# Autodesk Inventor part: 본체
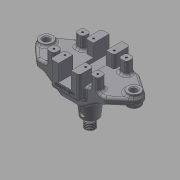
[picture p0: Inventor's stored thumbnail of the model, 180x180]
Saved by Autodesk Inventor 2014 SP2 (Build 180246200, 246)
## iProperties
Created: 2025-07
Part Number: 본체
Material: Generic
Document SubType Name: Modeling
Designer: Administrator
Density: 1 g/cm^3
Appearance: Default
Author: Administrator
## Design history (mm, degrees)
sketch "스케치8"
  geometry: L1 (-43.156, 23.794)-(43.156, 23.794); L2 (-43.156, 23.794)-(-61.618, 7.497); L3 (-60.673, -8.235)-(-40.394, -22.206); L4 (-40.394, -22.206)-(40.394, -22.206); L5 (43.156, 23.794)-(61.618, 7.497); L6 (40.394, -22.206)-(60.673, -8.235); L7 (-18, -12.206)-(18, -12.206); L8 (18, -12.206)-(18, -32.155); L9 (18, -32.155)-(-18, -32.155); L10 (-18, -32.155)-(-18, -12.206); L11 (-18, 31.845)-(18, 31.845); L12 (18, 31.845)-(18, 13.794); L13 (18, 13.794)-(-18, 13.794); L14 (-18, 13.794)-(-18, 31.845); L15 (23.496, -12.206)-(33.496, -12.206); L16 (33.496, -12.206)-(33.496, -22.206); L17 (33.496, -22.206)-(23.496, -22.206); L18 (23.496, -22.206)-(23.496, -12.206); L19 (-31.504, -22.206)-(-31.504, -12.206); L20 (-31.504, -12.206)-(-21.504, -12.206); L21 (-21.504, -12.206)-(-21.504, -22.206); L22 (-21.504, -22.206)-(-31.504, -22.206); L23 (23.496, 13.794)-(23.496, 23.794); L24 (23.496, 23.794)-(33.496, 23.794); L25 (33.496, 23.794)-(33.496, 13.794); L26 (33.496, 13.794)-(23.496, 13.794); L27 (-31.504, 13.794)-(-31.504, 23.794); L28 (-31.504, 23.794)-(-21.504, 23.794); L29 (-21.504, 23.794)-(-21.504, 13.794); L30 (-21.504, 13.794)-(-31.504, 13.794); A1 r 10 centre (55, 0) between (60.673, -8.235) and (61.618, 7.497); A2 r 10 centre (-55, 0) between (-61.618, 7.497) and (-60.673, -8.235); 11 further points
  constraints: 60 end point, 7 midpoint, 7 parallel, 5 horizontal, 4 horizontal alignment, 4 point on circle, 4 tangent, 4 vertical alignment, 3 perpendicular, 2 centre point, 2 equal length, 1 point on line, 1 vertical, 27 other
  dimensions: "d47" = 20 diameter of A2; "d48" = 20 diameter of A1; "d49" = 110 distance of A1.centre A2.centre; "d50" = 46 distance between parallel lines of L4 L1; "d52" = 76 deg angle of L3 L2; "d53" = 64 distance between parallel lines of L9 L11; "d54" = 36 distance of L7.start L7.end; "d55" = 36 distance of L12.end L13.end; "d56" = 10 distance of L15.start L15.end; "d57" = 10 distance of L15.end L16.end; "d60" = 55 distance of L17.end L19.start; "d63" = 36 distance of L17.end L23.start; "d105" = 86.31171 distance of L1.start L1.end
extrude "돌출2" new body sketch "스케치8" distance "d66" = 16; taper "d67" = 0 deg
extrude "돌출3" join sketch "스케치8" distance "d68" = 16; taper "d69" = 0 deg
extrude "돌출4" join sketch "스케치8" distance "d70" = 25; taper "d71" = 0 deg
extrude "돌출5" join sketch "스케치8" distance "d72" = 15; taper "d73" = 0 deg
extrude "돌출6" join sketch "스케치8" distance "d74" = 25; taper "d75" = 0 deg
sketch "스케치9"
  geometry: L1 (19.66, -41)-(-66.652, -41) reference; L2 (-66.652, -41)-(-66.652, -16) reference; L3 (-66.652, -16)-(-55, -16) reference; L4 (-55, -16)-(-55, 0) reference; L5 (-55, 0)-(-45, 0) reference; L6 (-45, 0)-(-45, -16) reference; L7 (-45, -16)-(-41.496, -16) reference; L8 (-41.496, -31)-(-41.496, -16) reference; L9 (-5.496, -31)-(-41.496, -31) reference; L10 (-5.496, -16)-(-5.496, -31) reference; L11 (-5.496, 0)-(-5.496, -16) reference; L12 (-41.496, 0)-(-5.496, 0) reference; L13 (-41.496, -16)-(-41.496, 0) reference; L14 (19.66, -16)-(19.66, -41) reference; L15 (10, -16)-(19.66, -16) reference; L16 (10, 0)-(10, -16) reference; L17 (0, 0)-(10, 0) reference; L18 (0, -16)-(0, 0) reference; L19 (-5.496, -16)-(0, -16) reference; L20 (-39.496, -41)-(-7.496, -41); L21 (-7.496, -41)-(15.354, -25); L22 (-39.496, -41)-(-62.347, -25); L23 (-66.652, -16)-(-55, -16) reference; L24 (-55, -16)-(-55, 0) reference; L25 (-55, 0)-(-45, 0) reference; L26 (-45, 0)-(-45, -16) reference; L27 (-45, -16)-(-41.496, -16) reference; L28 (-41.496, -31)-(-41.496, -16) reference; L29 (-5.496, -31)-(-41.496, -31) reference; L30 (-5.496, -16)-(-5.496, -31) reference; L31 (-5.496, 0)-(-5.496, -16) reference; L32 (-41.496, 0)-(-5.496, 0) reference; L33 (-41.496, -16)-(-41.496, 0) reference; L34 (10, -16)-(19.66, -16) reference; L35 (10, 0)-(10, -16) reference; L36 (0, 0)-(10, 0) reference; L37 (0, -16)-(0, 0) reference; L38 (-5.496, -16)-(0, -16) reference; L39 (15.354, -25)-(37.491, -25); L40 (-7.496, -41)-(37.491, -41); L41 (-62.347, -25)-(-88.573, -25); L42 (-88.573, -25)-(-88.573, -41); L43 (-88.573, -41)-(-39.496, -41); L44 (19.66, -16)-(19.66, -41) reference; L45 (19.66, -41)-(-66.652, -41) reference; L46 (-66.652, -41)-(-66.652, -16) reference; L47 (37.491, -25)-(47.678, -25); L48 (47.678, -25)-(47.678, -41); L49 (47.678, -41)-(37.491, -41); 2 further points
  constraints: 22 end point, 4 parallel, 3 perpendicular, 2 point on line, 1 midpoint, 1 vertical alignment
  dimensions: "d76" = 32 distance of L20.start L20.end; "d79" = 35 deg angle of L20 L21; "d80" = 9 vertical distance of L14.start L21.end; "d81" = 35 deg angle of L20 L22; "d82" = 9 vertical distance of L2.end L22.end
extrude "돌출7" cut sketch "스케치9" stored distance "d83" = 25; taper "d84" = 0 deg
sketch "스케치10"
  geometry: L1 (-33.496, 23.794)-(-23.496, 23.794) reference; L2 (-23.496, 23.794)-(-23.496, 13.794) reference; L3 (-23.496, 13.794)-(-33.496, 13.794) reference; L4 (-33.496, 13.794)-(-33.496, 23.794) reference; L5 (21.504, 23.794)-(31.504, 23.794) reference; L6 (31.504, 23.794)-(31.504, 13.794) reference; L7 (31.504, 13.794)-(21.504, 13.794) reference; L8 (21.504, 13.794)-(21.504, 23.794) reference; L9 (18, -12.206)-(18, -32.155) reference; L10 (18, -32.155)-(-18, -32.155) reference; L11 (-18, -32.155)-(-18, -12.206) reference; L12 (-18, -12.206)-(18, -12.206) reference; L13 (18, 31.845)-(18, 13.794) reference; L14 (18, 13.794)-(-18, 13.794) reference; L15 (-18, 13.794)-(-18, 31.845) reference; L16 (-18, 31.845)-(18, 31.845) reference; L17 (-23.496, -12.206)-(-23.496, -22.206) reference; L18 (-23.496, -22.206)-(-33.496, -22.206) reference; L19 (-33.496, -22.206)-(-33.496, -12.206) reference; L20 (-33.496, -12.206)-(-23.496, -12.206) reference; L21 (31.504, -22.206)-(21.504, -22.206) reference; L22 (21.504, -22.206)-(21.504, -12.206) reference; L23 (21.504, -12.206)-(31.504, -12.206) reference; L24 (31.504, -12.206)-(31.504, -22.206) reference; L25 (-8, 31.845)-(8, 31.845); L26 (8, 31.845)-(8, -32.155); L27 (8, -32.155)-(-8, -32.155); L28 (-8, -32.155)-(-8, 31.845); 2 further points
  constraints: 8 end point, 2 parallel, 2 point on line, 1 horizontal, 1 midpoint, 1 perpendicular, 1 vertical alignment
  dimensions: "d85" = 16 distance of L25.start L25.end
extrude "돌출8" cut sketch "스케치10" distance "d86" = 21; taper "d87" = 0 deg
sketch "스케치11"
  geometry: L1 (18, -32.155)-(8, -32.155) reference; L2 (8, -32.155)-(8, -12.206) reference; L3 (21.504, -22.206)-(21.504, -12.206) reference; L4 (60.673, -8.235)-(40.394, -22.206) reference; L5 (43.156, 23.794)-(61.618, 7.497) reference; L6 (18, 23.794)-(18, 13.794) reference; L7 (8, 13.794)-(8, 31.845) reference; L8 (8, 31.845)-(18, 31.845) reference; L9 (18, 31.845)-(18, 23.794) reference; L10 (8, -12.206)-(8, 13.794) reference; L11 (31.504, -22.206)-(21.504, -22.206) reference; L12 (-61.618, 7.497)-(-43.156, 23.794) reference; L13 (-40.394, -22.206)-(-60.673, -8.235) reference; L14 (-18, -22.206)-(-18, -12.206) reference; L15 (-18, -12.206)-(-8, -12.206) reference; L16 (-8, -12.206)-(-8, -32.155) reference; L17 (-8, -32.155)-(-18, -32.155) reference; L18 (-18, -32.155)-(-18, -22.206) reference; L19 (-18, 13.794)-(-18, 23.794) reference; L20 (-8, 31.845)-(-8, 13.794) reference; L21 (-18, 31.845)-(-8, 31.845) reference; L22 (-18, 23.794)-(-18, 31.845) reference; L23 (-8, 13.794)-(-8, -12.206) reference; L24 (40.394, -22.206)-(31.504, -22.206) reference; L25 (-43.156, 23.794)-(-33.496, 23.794) reference; L26 (21.504, -12.206)-(31.504, -12.206) reference; L27 (31.504, -12.206)-(31.504, -22.206) reference; L28 (18, 13.794)-(8, 13.794) reference; L29 (21.504, 23.794)-(31.504, 23.794) reference; L30 (21.504, 13.794)-(21.504, 23.794) reference; L31 (31.504, 13.794)-(21.504, 13.794) reference; L32 (31.504, 23.794)-(31.504, 13.794) reference; L33 (-8, 13.794)-(-18, 13.794) reference; L34 (21.504, -22.206)-(18, -22.206) reference; L35 (18, -12.206)-(18, -22.206) reference; L36 (18, -22.206)-(18, -32.155) reference; L37 (8, -12.206)-(18, -12.206) reference; L38 (31.504, 23.794)-(43.156, 23.794) reference; L39 (18, 23.794)-(21.504, 23.794) reference; L40 (-23.496, -12.206)-(-23.496, -22.206) reference; L41 (-18, -22.206)-(-23.496, -22.206) reference; L42 (-33.496, -12.206)-(-23.496, -12.206) reference; L43 (-33.496, -22.206)-(-33.496, -12.206) reference; L44 (-23.496, -22.206)-(-33.496, -22.206) reference; L45 (-33.496, -22.206)-(-40.394, -22.206) reference; L46 (-33.496, 23.794)-(-23.496, 23.794) reference; L47 (-23.496, 23.794)-(-18, 23.794) reference; L48 (-33.496, 13.794)-(-33.496, 23.794) reference; L49 (-23.496, 13.794)-(-33.496, 13.794) reference; L50 (-23.496, 23.794)-(-23.496, 13.794) reference; C1 r 8 at (-55, 0); C2 r 8 at (55, 0); A1 r 10 centre (55, 0) between (60.673, -8.235) and (61.618, 7.497) reference; A2 r 10 centre (-55, 0) between (-61.618, 7.497) and (-60.673, -8.235) reference; 1 further point
  constraints: 2 centre point, 1 coincident
  dimensions: "d97" = 16 diameter of C1; "d98" = 16 diameter of C2; "d99" = 110 distance of C1.centre C2.centre
  node "절단 모서리 투영7"
extrude "돌출9" join sketch "스케치11" distance "d100" = 3; taper "d101" = 0 deg
extrude "돌출10" join sketch "스케치11" distance "d102" = 12; taper "d103" = 0 deg
sketch "스케치12"
  geometry: L1 (-5.496, -31)-(-41.496, -31) reference; L2 (-41.496, -31)-(-41.496, -16) reference; L3 (-45, -16)-(-41.496, -16) reference; L4 (-45, 0)-(-45, -16) reference; L5 (-55, 0)-(-45, 0) reference; L6 (-55, -16)-(-55, 0) reference; L7 (-66.652, -16)-(-55, -16) reference; L8 (-66.652, -25)-(-66.652, -16) reference; L9 (-62.347, -25)-(-66.652, -25) reference; L10 (-39.496, -41)-(-62.347, -25) reference; L11 (-7.496, -41)-(-39.496, -41) reference; L12 (15.354, -25)-(-7.496, -41) reference; L13 (19.66, -25)-(15.354, -25) reference; L14 (19.66, -16)-(19.66, -25) reference; L15 (10, -16)-(19.66, -16) reference; L16 (10, 0)-(10, -16) reference; L17 (0, 0)-(10, 0) reference; L18 (0, -16)-(0, 0) reference; L19 (-5.496, -16)-(0, -16) reference; L20 (-5.496, 0)-(-5.496, -16) reference; L21 (-15.496, 0)-(-5.496, 0) reference; L22 (-15.496, -21)-(-15.496, 0) reference; L23 (-31.496, -21)-(-15.496, -21) reference; L24 (-31.496, 0)-(-31.496, -21) reference; L25 (-41.496, 0)-(-31.496, 0) reference; L26 (-41.496, -16)-(-41.496, 0) reference; L27 (-5.496, -16)-(-5.496, -31) reference; 1 further point
  node "절단 모서리 투영8"
fillet "모깎기10" dims "d106" = 3
fillet "모깎기11" dims "d107" = 3
fillet "모깎기12" dims "d108" = 3
fillet "모깎기13" dims "d109" = 3
fillet "모깎기14" dims "d110" = 3
fillet "모깎기15" dims "d111" = 3
fillet "모깎기16" dims "d112" = 3
fillet "모깎기17" dims "d113" = 3
fillet "모깎기18" dims "d114" = 3
fillet "모깎기19" dims "d115" = 3
fillet "모깎기20" dims "d116" = 3
fillet "모깎기21" dims "d117" = 3
sketch "스케치13"
  geometry: L1 (-26.496, -22.206)-(-30.496, -22.206) reference; L2 (-33.496, -19.206)-(-33.496, -15.206) reference; L3 (-30.496, -12.206)-(-26.496, -12.206) reference; L4 (-23.496, -15.206)-(-23.496, -19.206) reference; L5 (-15, 31.845)-(-8, 31.845) reference; L6 (-8, 31.845)-(-8, 13.794) reference; L7 (-8, 13.794)-(-18, 13.794) reference; L8 (-18, 13.794)-(-18, 28.845) reference; L9 (18, 28.845)-(18, 16.794) reference; L10 (15, 13.794)-(8, 13.794) reference; L11 (8, 13.794)-(8, 31.845) reference; L12 (8, 31.845)-(15, 31.845) reference; L13 (24.504, -12.206)-(28.504, -12.206) reference; L14 (31.504, -15.206)-(31.504, -19.206) reference; L15 (28.504, -22.206)-(24.504, -22.206) reference; L16 (21.504, -19.206)-(21.504, -15.206) reference; L17 (21.504, 16.794)-(21.504, 20.794) reference; L18 (24.504, 23.794)-(28.504, 23.794) reference; L19 (31.504, 20.794)-(31.504, 16.794) reference; L20 (28.504, 13.794)-(24.504, 13.794) reference; L21 (-33.496, 16.794)-(-33.496, 20.794) reference; L22 (-30.496, 23.794)-(-26.496, 23.794) reference; L23 (-23.496, 20.794)-(-23.496, 16.794) reference; L24 (-26.496, 13.794)-(-30.496, 13.794) reference; L25 (-8, -12.206)-(-8, -32.155) reference; L26 (-8, -32.155)-(-18, -32.155) reference; L27 (-18, -32.155)-(-18, -12.206) reference; L28 (-18, -12.206)-(-8, -12.206) reference; L29 (8, -32.155)-(8, -12.206) reference; L30 (8, -12.206)-(15, -12.206) reference; L31 (18, -15.206)-(18, -29.155) reference; L32 (15, -32.155)-(8, -32.155) reference; C1 r 4 at (-55, 0); C2 r 4 at (55, 0); A1 r 8 centre (55, 0) between (53.743, 7.901) and (52.806, -7.693) reference; A2 r 8 centre (55, 0) between (52.806, -7.693) and (53.743, 7.901) reference; A3 r 8 centre (-55, 0) between (-52.806, -7.693) and (-53.743, 7.901) reference; A4 r 8 centre (-55, 0) between (-53.743, 7.901) and (-52.806, -7.693) reference; A5 r 3 centre (-26.496, -19.206) between (-26.496, -22.206) and (-23.496, -19.206) reference; A6 r 3 centre (-30.496, -19.206) between (-33.25, -20.397) and (-30.628, -22.203) reference; A7 r 3 centre (-30.496, -19.206) between (-30.628, -22.203) and (-30.496, -22.206) reference; A8 r 3 centre (-30.496, -19.206) between (-33.496, -19.206) and (-33.25, -20.397) reference; A9 r 3 centre (-30.496, -15.206) between (-30.496, -12.206) and (-33.496, -15.206) reference; A10 r 3 centre (-26.496, -15.206) between (-23.496, -15.206) and (-26.496, -12.206) reference; A11 r 3 centre (-15, 28.845) between (-15, 31.845) and (-18, 28.845) reference; A12 r 3 centre (15, 16.794) between (15, 13.794) and (18, 16.794) reference; A13 r 3 centre (15, 28.845) between (18, 28.845) and (15, 31.845) reference; A14 r 3 centre (24.504, -15.206) between (24.504, -12.206) and (21.504, -15.206) reference; A15 r 3 centre (28.504, -15.206) between (31.504, -15.206) and (28.504, -12.206) reference; A16 r 3 centre (28.504, -19.206) between (28.504, -22.206) and (31.504, -19.206) reference; A17 r 3 centre (24.504, -19.206) between (21.504, -19.206) and (24.504, -22.206) reference; A18 r 3 centre (24.504, 16.794) between (21.504, 16.794) and (24.504, 13.794) reference; A19 r 3 centre (24.504, 20.794) between (24.504, 23.794) and (21.504, 20.794) reference; A20 r 3 centre (28.504, 20.794) between (31.504, 20.794) and (28.504, 23.794) reference; A21 r 3 centre (28.504, 16.794) between (28.504, 13.794) and (31.504, 16.794) reference; A22 r 3 centre (-30.496, 16.794) between (-33.496, 16.794) and (-30.496, 13.794) reference; A23 r 3 centre (-30.496, 20.794) between (-30.496, 23.794) and (-33.496, 20.794) reference; A24 r 3 centre (-26.496, 20.794) between (-23.496, 20.794) and (-26.496, 23.794) reference; A25 r 3 centre (-26.496, 16.794) between (-26.496, 13.794) and (-23.496, 16.794) reference; A26 r 3 centre (15, -15.206) between (18, -15.206) and (15, -12.206) reference; A27 r 3 centre (15, -29.155) between (15, -32.155) and (18, -29.155) reference; 1 further point
  constraints: 2 centre point, 2 coincident
  dimensions: "d118" = 8 diameter of C1; "d119" = 8 diameter of C2
hole "구멍1" sketch "스케치13" at (55, 0), (-55, 0) diameter "d120" = 8; stored, may be unused: countersink angle "d124" = 82 deg, drill point angle "d126" = 0 deg; dims "d121" = 6, "d122" = 3.023, "d123" = 2, "d125" = 8
chamfer "모따기1" distance "d127" = 1; stored, may be unused: second distance "d128" = 2, angle "d129" = 45 deg
chamfer "모따기2" distance "d130" = 1; stored, may be unused: second distance "d131" = 2, angle "d132" = 45 deg
chamfer "모따기3" distance "d133" = 1; stored, may be unused: second distance "d134" = 2, angle "d135" = 45 deg
chamfer "모따기4" distance "d136" = 1; stored, may be unused: second distance "d137" = 2, angle "d138" = 45 deg
sketch "스케치14"
  geometry: L1 (-15, 31.845)-(-8, 31.845) reference; L2 (-8, 31.845)-(-8, 13.794) reference; L3 (-8, 13.794)-(-18, 13.794) reference; L4 (-18, 13.794)-(-18, 28.845) reference; L5 (18, 28.845)-(18, 16.794) reference; L6 (15, 13.794)-(8, 13.794) reference; L7 (8, 13.794)-(8, 31.845) reference; L8 (8, 31.845)-(15, 31.845) reference; L9 (31.504, -15.206)-(31.504, -19.206) reference; L10 (28.504, -22.206)-(24.504, -22.206) reference; L11 (21.504, -19.206)-(21.504, -15.206) reference; L12 (24.504, -12.206)-(28.504, -12.206) reference; L13 (28.504, 13.794)-(24.504, 13.794) reference; L14 (21.504, 16.794)-(21.504, 20.794) reference; L15 (24.504, 23.794)-(28.504, 23.794) reference; L16 (31.504, 20.794)-(31.504, 16.794) reference; L17 (-23.496, -15.206)-(-23.496, -19.206) reference; L18 (-26.496, -22.206)-(-30.496, -22.206) reference; L19 (-33.496, -19.206)-(-33.496, -15.206) reference; L20 (-30.496, -12.206)-(-26.496, -12.206) reference; L21 (-26.496, 13.794)-(-30.496, 13.794) reference; L22 (-33.496, 16.794)-(-33.496, 20.794) reference; L23 (-30.496, 23.794)-(-26.496, 23.794) reference; L24 (-23.496, 20.794)-(-23.496, 16.794) reference; L25 (-8, -12.206)-(-8, -32.155) reference; L26 (-8, -32.155)-(-18, -32.155) reference; L27 (-18, -32.155)-(-18, -12.206) reference; L28 (-18, -12.206)-(-8, -12.206) reference; L29 (8, -32.155)-(8, -12.206) reference; L30 (8, -12.206)-(15, -12.206) reference; L31 (18, -15.206)-(18, -29.155) reference; L32 (15, -32.155)-(8, -32.155) reference; A1 r 3 centre (-15, 28.845) between (-15, 31.845) and (-18, 28.845) reference; A2 r 3 centre (15, 16.794) between (15, 13.794) and (18, 16.794) reference; A3 r 3 centre (15, 28.845) between (18, 28.845) and (15, 31.845) reference; A4 r 3 centre (28.504, -15.206) between (31.504, -15.206) and (28.504, -12.206) reference; A5 r 3 centre (28.504, -19.206) between (28.504, -22.206) and (31.504, -19.206) reference; A6 r 3 centre (24.504, -19.206) between (21.504, -19.206) and (24.504, -22.206) reference; A7 r 3 centre (24.504, -15.206) between (24.504, -12.206) and (21.504, -15.206) reference; A8 r 3 centre (28.504, 16.794) between (28.504, 13.794) and (31.504, 16.794) reference; A9 r 3 centre (24.504, 16.794) between (21.504, 16.794) and (24.504, 13.794) reference; A10 r 3 centre (24.504, 20.794) between (24.504, 23.794) and (21.504, 20.794) reference; A11 r 3 centre (28.504, 20.794) between (31.504, 20.794) and (28.504, 23.794) reference; A12 r 3 centre (-26.496, -15.206) between (-23.496, -15.206) and (-26.496, -12.206) reference; A13 r 3 centre (-26.496, -19.206) between (-26.496, -22.206) and (-23.496, -19.206) reference; A14 r 3 centre (-30.496, -19.206) between (-33.496, -19.206) and (-30.496, -22.206) reference; A15 r 3 centre (-30.496, -15.206) between (-30.496, -12.206) and (-33.496, -15.206) reference; A16 r 3 centre (-26.496, 16.794) between (-26.496, 13.794) and (-23.496, 16.794) reference; A17 r 3 centre (-30.496, 16.794) between (-33.496, 16.794) and (-30.496, 13.794) reference; A18 r 3 centre (-30.496, 20.794) between (-30.496, 23.794) and (-33.496, 20.794) reference; A19 r 3 centre (-26.496, 20.794) between (-23.496, 20.794) and (-26.496, 23.794) reference; A20 r 3 centre (15, -15.206) between (18, -15.206) and (15, -12.206) reference; A21 r 3 centre (15, -29.155) between (15, -32.155) and (18, -29.155) reference; 9 further points
  dimensions: "d139" = 26 distance of point (-13.26, 18.794) point (12.74, 18.794); "d140" = 5 distance from line of L15 point (26.504, 18.794); "d141" = 5 distance from line of L14 point (26.504, 18.794); "d142" = 5 distance from line of L9 point (26.504, -17.206); "d143" = 5 distance from line of L12 point (26.504, -17.206); "d144" = 26 distance of point (-13.26, -17.206) point (12.74, -17.206); "d145" = 5 distance from line of L20 point (-28.496, -17.206); "d146" = 5 distance from line of L17 point (-28.496, -17.206); "d147" = 5 distance from line of L24 point (-28.496, 18.794); "d148" = 5 distance from line of L21 point (-28.496, 18.794); "d149" = 36 distance of point (12.74, 18.794) point (12.74, -17.206); "d150" = 5 distance from line of L30 point (12.74, -17.206)
hole "구멍2" sketch "스케치14" at (-28.496, 18.794), (26.504, 18.794), (12.74, 18.794), (-13.26, 18.794), (-13.26, -17.206), (12.74, -17.206), (26.504, -17.206), (-28.496, -17.206) diameter "d151" = 2.459; stored, may be unused: countersink angle "d155" = 90 deg, drill point angle "d157" = 118 deg; dims "d152" = 6, "d153" = 6.3, "d154" = 2, "d156" = 8
fillet "모깎기22" dims "d158" = 3
fillet "모깎기23" dims "d159" = 3
node "작업 평면3"
sketch "스케치15"
  geometry: L1 (-65, 3)-(-65, 6) reference; L2 (-63, 10.472)-(-63, 12) reference; L3 (-63, 12)-(-60, 12) reference; L4 (-60, 12)-(-59, 11) reference; L5 (-59, 11)-(-59, -2) reference; L6 (-59, -2)-(-60, -3) reference; L7 (-60, -3)-(-63, -3) reference; L8 (-63, -3)-(-63, -1.472) reference; L9 (63, -1.472)-(63, -3) reference; L10 (63, -3)-(60, -3) reference; L11 (60, -3)-(59, -2) reference; L12 (59, -2)-(59, 11) reference; L13 (59, 11)-(60, 12) reference; L14 (60, 12)-(63, 12) reference; L15 (63, 12)-(63, 10.472) reference; L16 (65, 6)-(65, 3) reference; L17 (-16, 25)-(16, 25) reference; L18 (16, 25)-(38.076, 9.543) reference; L19 (39.796, 9)-(44, 9) reference; L20 (47, 12)-(50, 12) reference; L21 (50, 12)-(51, 11) reference; L22 (51, 11)-(51, -2) reference; L23 (51, -2)-(50, -3) reference; L24 (50, -3)-(47, -3) reference; L25 (44, 0)-(8, 0) reference; L26 (8, 0)-(8, 5) reference; L27 (8, 5)-(-8, 5) reference; L28 (-8, 5)-(-8, 0) reference; L29 (-8, 0)-(-44, 0) reference; L30 (-47, -3)-(-50, -3) reference; L31 (-50, -3)-(-51, -2) reference; L32 (-51, -2)-(-51, 11) reference; L33 (-51, 11)-(-50, 12) reference; L34 (-50, 12)-(-47, 12) reference; L35 (-44, 9)-(-39.796, 9) reference; L36 (-38.076, 9.543)-(-16, 25) reference; L37 (0, 25)-(0, 66); L38 (-12.5, 25)-(-12.5, 29); L39 (-12.5, 29)-(-10, 52); L40 (-10, 52)-(0, 52); L41 (-4.7, 55)-(0, 55); L42 (-4.7, 55)-(-4.7, 52); L43 (-65, 3)-(-65, 6) reference; L44 (-63, 10.472)-(-63, 12) reference; L45 (-63, 12)-(-60, 12) reference; L46 (-60, 12)-(-59, 11) reference; L47 (-59, 11)-(-59, -2) reference; L48 (-59, -2)-(-60, -3) reference; L49 (-60, -3)-(-63, -3) reference; L50 (-63, -3)-(-63, -1.472) reference; L51 (63, -1.472)-(63, -3) reference; L52 (63, -3)-(60, -3) reference; L53 (60, -3)-(59, -2) reference; L54 (59, -2)-(59, 11) reference; L55 (59, 11)-(60, 12) reference; L56 (60, 12)-(63, 12) reference; L57 (63, 12)-(63, 10.472) reference; L58 (65, 6)-(65, 3) reference; L59 (-16, 25)-(16, 25) reference; L60 (16, 25)-(38.076, 9.543) reference; L61 (39.796, 9)-(44, 9) reference; L62 (47, 12)-(50, 12) reference; L63 (50, 12)-(51, 11) reference; L64 (51, 11)-(51, -2) reference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; A1 r 3 centre (-66, -1.472) between (-63, -1.472) and (-64, 0.764) reference; A2 r 3 centre (-62, 3) between (-65, 3) and (-64, 0.764) reference; A3 r 3 centre (-62, 6) between (-64, 8.236) and (-65, 6) reference; A4 r 3 centre (-66, 10.472) between (-64, 8.236) and (-63, 10.472) reference; A5 r 3 centre (66, -1.472) between (64, 0.764) and (63, -1.472) reference; A6 r 3 centre (66, 10.472) between (63, 10.472) and (64, 8.236) reference; A7 r 3 centre (62, 6) between (65, 6) and (64, 8.236) reference; A8 r 3 centre (62, 3) between (64, 0.764) and (65, 3) reference; A9 r 3 centre (39.796, 12) between (38.076, 9.543) and (39.796, 9) reference; A10 r 3 centre (44, 12) between (44, 9) and (47, 12) reference; A11 r 3 centre (44, -3) between (47, -3) and (44, 0) reference; A12 r 3 centre (-44, -3) between (-44, 0) and (-47, -3) reference; A13 r 3 centre (-44, 12) between (-47, 12) and (-44, 9) reference; A14 r 3 centre (-39.796, 12) between (-39.796, 9) and (-38.076, 9.543) reference; A15 r 3 centre (-66, -1.472) between (-63, -1.472) and (-64, 0.764) reference; A16 r 3 centre (-62, 3) between (-65, 3) and (-64, 0.764) reference; A17 r 3 centre (-62, 6) between (-64, 8.236) and (-65, 6) reference; A18 r 3 centre (-66, 10.472) between (-64, 8.236) and (-63, 10.472) reference; A19 r 3 centre (66, -1.472) between (64, 0.764) and (63, -1.472) reference; A20 r 3 centre (66, 10.472) between (63, 10.472) and (64, 8.236) reference; A21 r 3 centre (62, 6) between (65, 6) and (64, 8.236) reference; A22 r 3 centre (62, 3) between (64, 0.764) and (65, 3) reference; A23 r 3 centre (39.796, 12) between (38.076, 9.543) and (39.796, 9) reference; A24 r 3 centre (44, 12) between (44, 9) and (47, 12) reference; A25 r 3 centre (44, -3) between (47, -3) and (44, 0) reference; A26 r 3 centre (-44, -3) between (-44, 0) and (-47, -3) reference; A27 r 3 centre (-44, 12) between (-47, 12) and (-44, 9) reference; A28 r 3 centre (-39.796, 12) between (-39.796, 9) and (-38.076, 9.543) reference; 2 further points
  constraints: 20 end point, 5 perpendicular, 4 point on line, 3 parallel, 2 midpoint
  dimensions: "d163" = 4 distance of L38.start L38.end; "d166" = 25 diameter of L38 L37; "d171" = 20 diameter of L39.end L37; "d172" = 9.4 diameter of L42 L37; "d175" = 23 vertical distance of L39.end L38.end; "d176" = 3 distance of L41.start L42.end; "d177" = 12 diameter of L79 L37; "d178" = 30 deg angle of L79 L80; "d181" = 41 distance of L37.end L37.start; "d182" = 30 deg angle of L82 L81; "d183" = 9.4 diameter of L81.end L37
  node "절단 모서리 투영11"
  node "절단 모서리 투영13"
revolve "회전3" stored, may be unused: angle "d168" = 180 deg
revolve "회전4" stored, may be unused: angle "d184" = 180 deg
feature "스레드1" dims "d185" = 10, "d186" = 0
sketch "스케치17"
  geometry: L1 (16, 21)-(23, 21) reference; 2 further points
  constraints: 1 vertical alignment, 1 other
  dimensions: "d187" = 24 distance from line of point (8, -3) L1
feature "엠보싱1" sketch "스케치17" dims "d47" = 20, "d48" = 20, "d49" = 110, "d50" = 46, "d52" = 76 deg, "d53" = 64, "d54" = 36, "d55" = 36, "d56" = 10, "d57" = 10, "d60" = 55, "d63" = 36, "d105" = 86.31171, "d188" = 0.5, "d189" = 0
node "작업 평면6"
  node "작업 평면5"
sketch "스케치18"
  geometry: L1 (-39.656, 12.199)-(-39.656, 22.919); L2 (-46.656, 12.199)-(-46.656, 22.919); L3 (-59.156, 1.105)-(-27.156, 1.105) reference; L4 (-27.156, 1.105)-(-5.08, -14.468) reference; L5 (-3.36, -15.015)-(3.513, -15.015) reference; L6 (7.629, -18.038)-(7.212, -21.06) reference; L7 (2.262, -24.083)-(-8.652, -24.083) reference; L8 (-11.652, -27.105)-(-11.652, -40.203) reference; L9 (-11.652, -40.203)-(-15.892, -40.203) reference; L10 (-17.412, -40.203)-(-21.652, -40.203) reference; L11 (-21.652, -40.203)-(-21.652, -27.105) reference; L12 (-24.652, -24.083)-(-25.156, -24.083) reference; L13 (-25.156, -24.083)-(-25.156, -40.203) reference; L14 (-25.156, -40.203)-(-29.656, -40.203) reference; L15 (-31.176, -40.203)-(-35.156, -40.203) reference; L16 (-35.156, -40.203)-(-35.156, -19.045) reference; L17 (-35.156, -19.045)-(-51.156, -19.045) reference; L18 (-51.156, -19.045)-(-51.156, -40.203) reference; L19 (-51.156, -40.203)-(-55.656, -40.203) reference; L20 (-57.176, -40.203)-(-61.156, -40.203) reference; L21 (-61.156, -40.203)-(-61.156, -24.083) reference; L22 (-61.156, -24.083)-(-63.652, -24.083) reference; L23 (-66.652, -27.105)-(-66.652, -40.203) reference; L24 (-66.652, -40.203)-(-70.892, -40.203) reference; L25 (-72.412, -40.203)-(-76.652, -40.203) reference; L26 (-76.652, -40.203)-(-76.652, -27.105) reference; L27 (-79.652, -24.083)-(-88.573, -24.083) reference; L28 (-93.524, -21.06)-(-93.941, -18.038) reference; L29 (-89.825, -15.015)-(-82.952, -15.015) reference; L30 (-81.231, -14.468)-(-59.156, 1.105) reference; A1 r 3.5 centre (-43.156, 12.199) between (-46.656, 12.199) and (-39.656, 12.199); A2 r 3.5 centre (-43.156, 22.199) between (-39.656, 22.199) and (-46.656, 22.199); 28 further points; 19 other entities
  constraints: 4 end point, 4 horizontal alignment, 4 point on circle, 3 tangent, 2 centre point, 2 point on line, 1 parallel, 1 vertical, 1 vertical alignment, 19 other
  dimensions: "d192" = 7 diameter of A1; "d194" = 10 distance of A1.centre A2.centre; "d195" = 7.5 distance of point (-43.156, 29.699) A2.centre
extrude "돌출11" cut sketch "스케치18" distance "d196" = 4; taper "d197" = 0 deg
node "솔리드4"
node "작업 평면4"
node "절단 모서리 투영4"
node "절단 모서리 투영5"
node "절단 모서리 투영6"
node "절단 모서리 투영9"
node "절단 모서리 투영10"
node "절단 모서리 투영15"
other parameters: "d161" = 90 deg, "d190" = -7 deg, "d191" = -9
